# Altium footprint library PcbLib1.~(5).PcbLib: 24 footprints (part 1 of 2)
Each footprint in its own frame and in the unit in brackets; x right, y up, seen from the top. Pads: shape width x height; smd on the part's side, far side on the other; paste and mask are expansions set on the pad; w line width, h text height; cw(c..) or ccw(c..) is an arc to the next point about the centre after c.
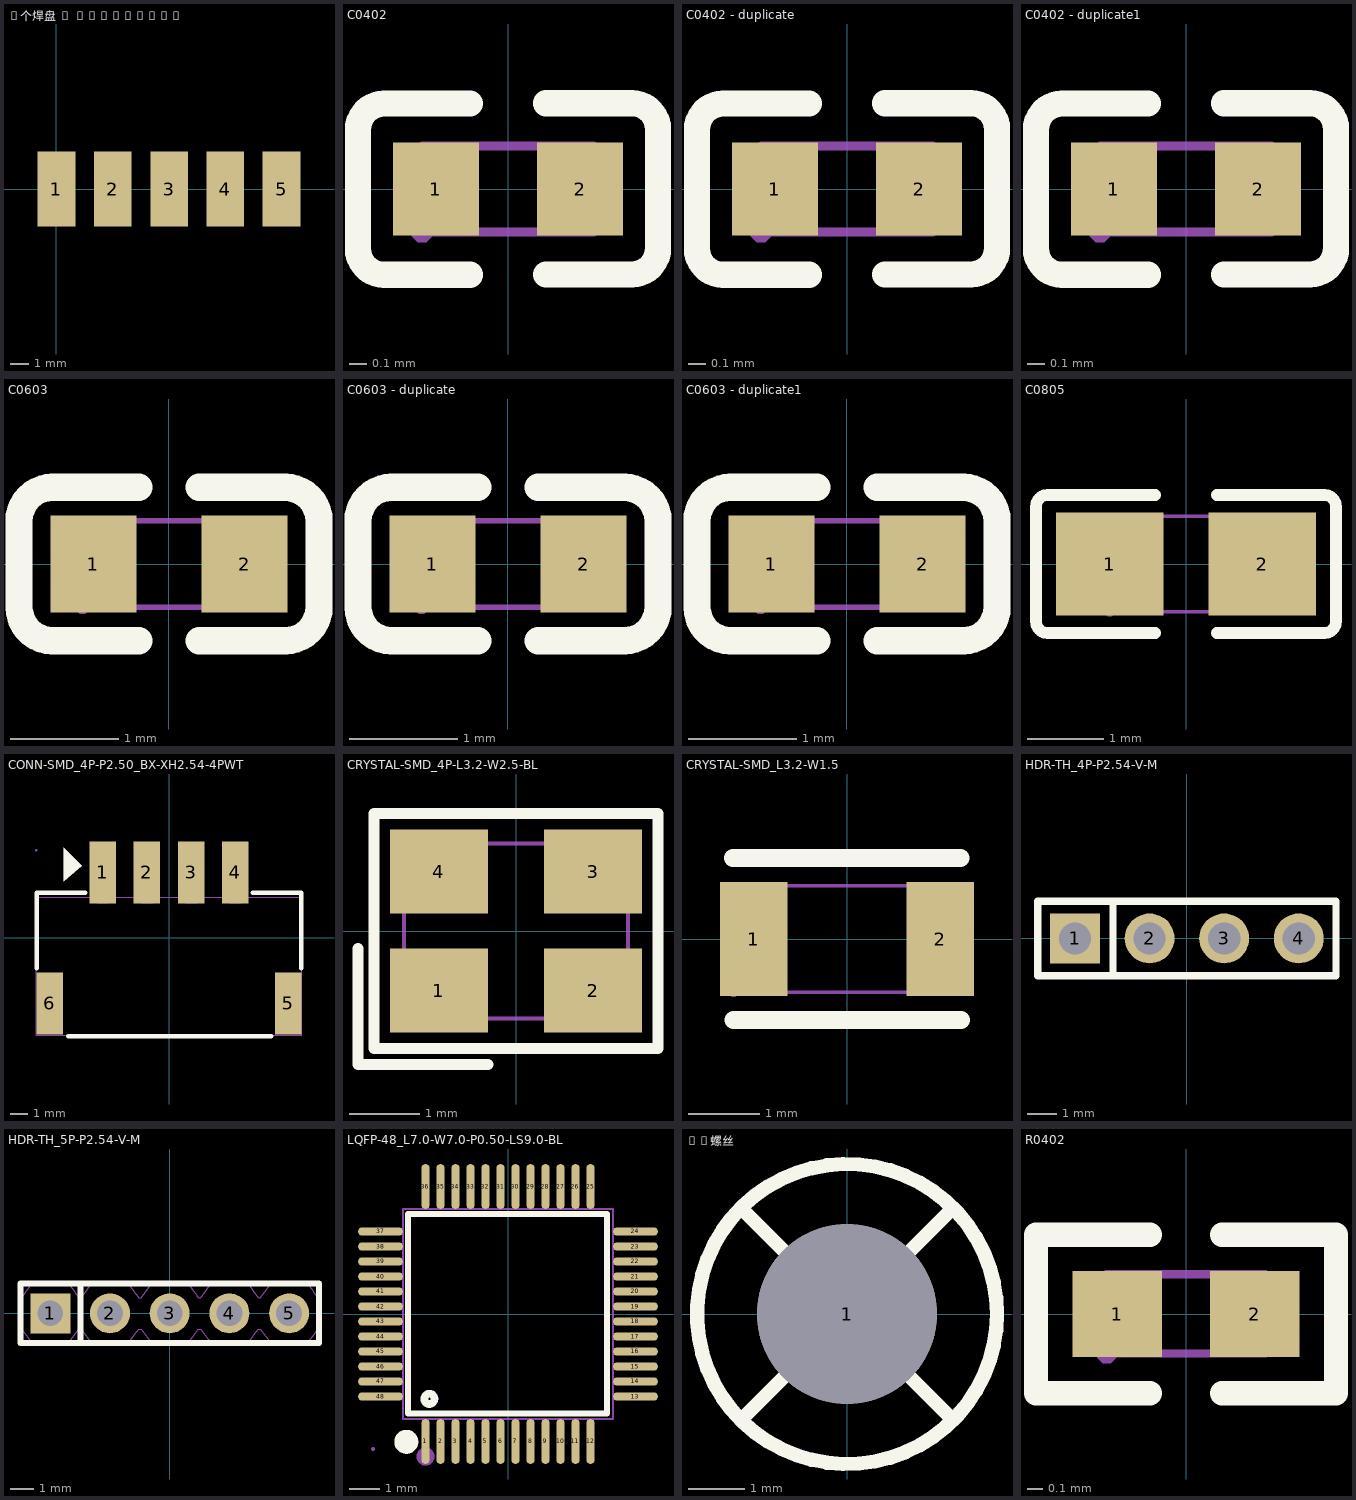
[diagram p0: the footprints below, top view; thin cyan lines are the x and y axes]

## 5个焊盘 - duplicate [mm]
pads (5):
  rect 2x4 smd: 1(0,0) 2(3,0) 3(6.001,0) 4(9,0) 5(12,0)

## C0402 [mm]
pads (2):
  rect 0.5x0.54 smd: 1(-0.42,0) 2(0.42,0)
Top Overlay:
  lines w0.152: -0.221,-0.5 -0.721,-0.5 cw(c-0.721,-0.347) -0.874,-0.347 -0.874,0.345 cw(c-0.721,0.345) -0.721,0.498 -0.221,0.498 ; 0.221,-0.498 0.721,-0.498 ccw(c0.721,-0.345) 0.874,-0.345 0.874,0.347 ccw(c0.721,0.347) 0.721,0.5 0.221,0.5
Mechanical 6:
  lines w0.051: -0.5,-0.25 0.5,-0.25 0.5,0.25 -0.5,0.25 -0.5,-0.25
Mechanical 8:
  region: -0.44,-0.25 -0.44,-0.275 -0.475,-0.31 -0.525,-0.31 -0.56,-0.275 -0.56,-0.25 -0.56,-0.225 -0.525,-0.19 -0.475,-0.19 -0.44,-0.225 -0.44,-0.25
Mechanical 9:
  region: 0.5,-0.25 0.5,0.25 0.25,0.25 0.25,-0.25
  region: -0.5,-0.25 -0.5,0.25 -0.25,0.25 -0.25,-0.25

## C0402 - duplicate [mm]
pads (2):
  rect 0.5x0.54 smd: 1(-0.42,0) 2(0.42,0)
Top Overlay:
  lines w0.152: -0.221,-0.5 -0.721,-0.5 cw(c-0.721,-0.347) -0.874,-0.347 -0.874,0.345 cw(c-0.721,0.345) -0.721,0.498 -0.221,0.498 ; 0.221,-0.498 0.721,-0.498 ccw(c0.721,-0.345) 0.874,-0.345 0.874,0.347 ccw(c0.721,0.347) 0.721,0.5 0.221,0.5
Mechanical 6:
  lines w0.051: -0.5,-0.25 -0.5,0.25 0.5,0.25 0.5,-0.25 -0.5,-0.25
Mechanical 8:
  region: -0.44,-0.25 -0.44,-0.275 -0.475,-0.31 -0.525,-0.31 -0.56,-0.275 -0.56,-0.25 -0.56,-0.225 -0.525,-0.19 -0.475,-0.19 -0.44,-0.225 -0.44,-0.25
Mechanical 9:
  region: -0.5,-0.25 -0.5,0.25 -0.25,0.25 -0.25,-0.25
  region: 0.5,-0.25 0.5,0.25 0.25,0.25 0.25,-0.25

## C0402 - duplicate1 [mm]
pads (2):
  rect 0.5x0.54 smd: 1(-0.42,0) 2(0.42,0)
Top Overlay:
  lines w0.152: -0.221,-0.5 -0.721,-0.5 cw(c-0.721,-0.347) -0.874,-0.347 -0.874,0.345 cw(c-0.721,0.345) -0.721,0.498 -0.221,0.498 ; 0.221,-0.498 0.721,-0.498 ccw(c0.721,-0.345) 0.874,-0.345 0.874,0.347 ccw(c0.721,0.347) 0.721,0.5 0.221,0.5
Mechanical 6:
  lines w0.051: -0.5,-0.25 -0.5,0.25 0.5,0.25 0.5,-0.25 -0.5,-0.25
Mechanical 8:
  region: -0.44,-0.25 -0.44,-0.275 -0.475,-0.31 -0.525,-0.31 -0.56,-0.275 -0.56,-0.25 -0.56,-0.225 -0.525,-0.19 -0.475,-0.19 -0.44,-0.225 -0.44,-0.25
Mechanical 9:
  region: -0.5,-0.25 -0.5,0.25 -0.25,0.25 -0.25,-0.25
  region: 0.5,-0.25 0.5,0.25 0.25,0.25 0.25,-0.25

## C0603 [mm]
pads (2):
  rect 0.8x0.9 smd: 1(-0.7,0) 2(0.7,0)
Top Overlay:
  lines w0.254: -1.08,-0.71 -0.28,-0.71 ; -1.08,0.71 -0.28,0.71 ; -1.08,-0.71 cw(c-1.08,-0.4) -1.39,-0.4 -1.39,0.4 cw(c-1.08,0.4) -1.08,0.71 ; 0.28,-0.71 1.08,-0.71 ccw(c1.08,-0.4) 1.39,-0.4 1.39,0.4 ccw(c1.08,0.4) 1.08,0.71 0.28,0.71
Mechanical 6:
  lines w0.051: -0.8,-0.4 0.8,-0.4 0.8,0.4 -0.8,0.4 -0.8,-0.4
Mechanical 8:
  region: -0.74,-0.4 -0.74,-0.425 -0.775,-0.46 -0.825,-0.46 -0.86,-0.425 -0.86,-0.4 -0.86,-0.375 -0.825,-0.34 -0.775,-0.34 -0.74,-0.375 -0.74,-0.4
Mechanical 9:
  region: 0.8,-0.4 0.8,0.4 0.5,0.4 0.5,-0.4
  region: -0.8,-0.4 -0.8,0.4 -0.5,0.4 -0.5,-0.4

## C0603 - duplicate [mm]
pads (2):
  rect 0.8x0.9 smd: 1(-0.7,0) 2(0.7,0)
Top Overlay:
  lines w0.254: -1.08,-0.71 -0.28,-0.71 ; -1.08,0.71 -0.28,0.71 ; -1.08,-0.71 cw(c-1.08,-0.4) -1.39,-0.4 -1.39,0.4 cw(c-1.08,0.4) -1.08,0.71 ; 0.28,-0.71 1.08,-0.71 ccw(c1.08,-0.4) 1.39,-0.4 1.39,0.4 ccw(c1.08,0.4) 1.08,0.71 0.28,0.71
Mechanical 6:
  lines w0.051: -0.8,-0.4 -0.8,0.4 0.8,0.4 0.8,-0.4 -0.8,-0.4
Mechanical 8:
  region: -0.74,-0.4 -0.74,-0.425 -0.775,-0.46 -0.825,-0.46 -0.86,-0.425 -0.86,-0.4 -0.86,-0.375 -0.825,-0.34 -0.775,-0.34 -0.74,-0.375 -0.74,-0.4
Mechanical 9:
  region: -0.8,-0.4 -0.8,0.4 -0.5,0.4 -0.5,-0.4
  region: 0.8,-0.4 0.8,0.4 0.5,0.4 0.5,-0.4

## C0603 - duplicate1 [mm]
pads (2):
  rect 0.8x0.9 smd: 1(-0.7,0) 2(0.7,0)
Top Overlay:
  lines w0.254: -1.08,-0.71 -0.28,-0.71 ; -1.08,0.71 -0.28,0.71 ; -1.08,-0.71 cw(c-1.08,-0.4) -1.39,-0.4 -1.39,0.4 cw(c-1.08,0.4) -1.08,0.71 ; 0.28,-0.71 1.08,-0.71 ccw(c1.08,-0.4) 1.39,-0.4 1.39,0.4 ccw(c1.08,0.4) 1.08,0.71 0.28,0.71
Mechanical 6:
  lines w0.051: -0.8,-0.4 -0.8,0.4 0.8,0.4 0.8,-0.4 -0.8,-0.4
Mechanical 8:
  region: -0.74,-0.4 -0.74,-0.425 -0.775,-0.46 -0.825,-0.46 -0.86,-0.425 -0.86,-0.4 -0.86,-0.375 -0.825,-0.34 -0.775,-0.34 -0.74,-0.375 -0.74,-0.4
Mechanical 9:
  region: -0.8,-0.4 -0.8,0.4 -0.5,0.4 -0.5,-0.4
  region: 0.8,-0.4 0.8,0.4 0.5,0.4 0.5,-0.4

## C0805 [mm]
pads (2):
  rect 1.41x1.35 smd paste-100 mask+0.051: 1(-1,0) 2(1,0)
Top Overlay:
  lines w0.152: -0.401,-0.904 -1.811,-0.904 cw(c-1.811,-0.751) -1.964,-0.751 -1.964,0.751 cw(c-1.811,0.751) -1.811,0.904 -0.401,0.904 ; 0.401,-0.904 1.811,-0.904 ccw(c1.811,-0.751) 1.964,-0.751 1.964,0.751 ccw(c1.811,0.751) 1.811,0.904 0.401,0.904
Top Paste:
  region: -1.705,-0.64 -1.705,0.64 -1.655,0.69 -0.505,0.69 -0.455,0.64 -0.45,0.23 -0.9,0.23 -0.9,-0.22 -0.46,-0.22 -0.455,-0.64 -0.505,-0.69 -1.655,-0.69
  region: 1.705,0.64 1.705,-0.64 1.655,-0.69 0.505,-0.69 0.455,-0.64 0.45,-0.23 0.9,-0.23 0.9,0.22 0.46,0.22 0.455,0.64 0.505,0.69 1.655,0.69
Mechanical 6:
  lines w0.051: -1,-0.625 -1,0.625 1,0.625 1,-0.625 -1,-0.625
Mechanical 8:
  region: -0.94,-0.625 -0.94,-0.65 -0.975,-0.685 -1.025,-0.685 -1.06,-0.65 -1.06,-0.625 -1.06,-0.6 -1.025,-0.565 -0.975,-0.565 -0.94,-0.6 -0.94,-0.625
Mechanical 9:
  region: -1,-0.625 -1,0.625 -0.5,0.625 -0.5,-0.625
  region: 1,0.625 1,-0.625 0.5,-0.625 0.5,0.625

## CONN-SMD_4P-P2.50_BX-XH2.54-4PWT [mm]
pads (6):
  rect 1.5x3.5 smd paste+0 mask+0.05: 1(-3.75,3.7) 2(-1.25,3.7) 3(1.25,3.7) 4(3.75,3.7) 5(6.73,-3.7) 6(-6.73,-3.7)
Top Overlay:
  region: -4.946,4.081 -5.962,5.097 -5.962,3.192
  lines w0.254: -7.486,-1.719 -7.486,2.557 -4.731,2.557 ; -5.708,-5.571 5.783,-5.571 ; 4.73,2.558 6.389,2.558 7.486,2.558 7.486,-1.719
Mechanical 2:
  region: -4.946,4.081 -5.962,5.097 -5.962,3.192
Mechanical 6:
  lines w0.051: -7.5,-5.502 7.5,-5.502 7.5,2.298 -7.5,2.298 -7.5,-5.502
Mechanical 8:
  region: -7.44,4.95 -7.44,4.925 -7.475,4.89 -7.525,4.89 -7.56,4.925 -7.56,4.95 -7.56,4.975 -7.525,5.01 -7.475,5.01 -7.44,4.975 -7.44,4.95
Mechanical 9:
  region: 6.53,-2.45 6.93,-2.45 6.93,-4.95 6.53,-4.95
  region: -6.93,-2.45 -6.53,-2.45 -6.53,-4.95 -6.93,-4.95
  region: 3.43,4.95 4.07,4.95 4.07,1.95 3.43,1.95
  region: 0.93,4.95 1.57,4.95 1.57,1.95 0.93,1.95
  region: -1.57,4.95 -0.93,4.95 -0.93,1.95 -1.57,1.95
  region: -4.07,4.95 -3.43,4.95 -3.43,1.95 -4.07,1.95

## CRYSTAL-SMD_4P-L3.2-W2.5-BL [mm]
pads (4):
  rect 1.4x1.2 smd: 1(-1.1,-0.85) 2(1.1,-0.85) 3(1.1,0.85) 4(-1.1,0.85)
Top Overlay:
  lines w0.152: -2.257,-0.25 -2.257,-1.907 -0.4,-1.907 ; -2.029,-1.678 -2.029,1.679 2.029,1.679 2.029,-1.678 -2.029,-1.678
Mechanical 2:
  circle w0.254: c-1.27,-0.889 r0.127
Mechanical 6:
  lines w0.051: -1.6,-1.25 -1.6,1.25 1.6,1.25 1.6,-1.25 -1.6,-1.25
Mechanical 8:
  region: -1.54,-1.25 -1.54,-1.275 -1.575,-1.31 -1.625,-1.31 -1.66,-1.275 -1.66,-1.25 -1.66,-1.225 -1.625,-1.19 -1.575,-1.19 -1.54,-1.225 -1.54,-1.25
Mechanical 9:
  region: -1.5,1.15 -0.6,1.15 -0.6,0.35 -1.5,0.35
  region: 0.6,1.15 1.5,1.15 1.5,0.35 0.6,0.35
  region: 0.6,-0.35 1.5,-0.35 1.5,-1.15 0.6,-1.15
  region: -1.5,-0.35 -0.6,-0.35 -0.6,-1.15 -1.5,-1.15

## CRYSTAL-SMD_L3.2-W1.5 [mm]
pads (2):
  rect 0.95x1.6 smd: 1(-1.308,0) 2(1.308,0)
Top Overlay:
  lines w0.254: -1.603,1.14 1.597,1.14 ; -1.597,-1.14 1.603,-1.14
Mechanical 6:
  lines w0.051: -1.597,-0.75 1.603,-0.75 1.603,0.75 -1.597,0.75 -1.597,-0.75
Mechanical 8:
  region: -1.537,-0.75 -1.537,-0.775 -1.573,-0.81 -1.622,-0.81 -1.657,-0.775 -1.657,-0.75 -1.657,-0.725 -1.622,-0.69 -1.573,-0.69 -1.537,-0.725 -1.537,-0.75
Mechanical 9:
  region: -1.598,-0.65 -1.598,0.65 -0.847,0.65 -0.847,-0.65
  region: 0.853,-0.65 0.853,0.65 1.603,0.65 1.603,-0.65

## HDR-TH_4P-P2.54-V-M [mm]
pads (4):
  rect 1.7x1.7 hole 1.1: 1(-3.81,0)
  round 1.7 hole 1.1: 2(-1.27,0) 3(1.27,0) 4(3.81,0)
Top Overlay:
  lines w0.254: -2.516,-1.27 -2.516,1.27 ; -2.516,1.27 -5.08,1.27 -5.08,-1.27 5.08,-1.27 5.08,1.27 -2.516,1.27
Mechanical 6:
  lines w0.051: -5.08,-1.25 5.08,-1.25 5.08,1.25 -5.08,1.25 -5.08,-1.25
Mechanical 8:
  region: -5.02,-1.25 -5.02,-1.275 -5.055,-1.31 -5.105,-1.31 -5.14,-1.275 -5.14,-1.25 -5.14,-1.225 -5.105,-1.19 -5.055,-1.19 -5.02,-1.225 -5.02,-1.25
Mechanical 9:
  region: 3.49,0.32 4.13,0.32 4.13,-0.32 3.49,-0.32
  region: 0.95,0.32 1.59,0.32 1.59,-0.32 0.95,-0.32
  region: -1.59,0.32 -0.95,0.32 -0.95,-0.32 -1.59,-0.32
  region: -4.13,0.32 -3.49,0.32 -3.49,-0.32 -4.13,-0.32

## HDR-TH_5P-P2.54-V-M [mm]
pads (5):
  rect 1.7x1.7 hole 1.1: 1(-5.08,0)
  round 1.7 hole 1.1: 2(-2.54,0) 3(0,0) 4(2.54,0) 5(5.08,0)
Top Overlay:
  lines w0.254: -3.786,-1.27 -3.786,1.27 ; -6.35,-1.27 -6.35,1.27 6.35,1.27 6.35,-1.27 -6.35,-1.27
Mechanical 6:
  lines w0.051: -6.35,-0.67 -6.35,-0.67 -6.3,-0.67 -5.85,-1.27 -4.31,-1.27 -4.077,-0.965 -3.86,-0.67 -3.76,-0.67 -3.31,-1.27 -1.77,-1.27 -1.542,-0.972 -1.503,-0.919 -1.32,-0.67 -1.22,-0.67 -0.77,-1.27 0.77,-1.27 0.992,-0.98 1.02,-0.942 1.22,-0.67 1.32,-0.67 1.77,-1.27 3.31,-1.271 3.51,-1.009 3.545,-0.963 3.581,-0.913 3.759,-0.67 3.86,-0.67 4.31,-1.27 5.85,-1.27 6.075,-0.976 6.3,-0.67 6.35,-0.67 6.35,0.67 6.3,0.67 6.112,0.925 6.079,0.97 5.85,1.27 4.311,1.27 3.86,0.67 3.76,0.67 3.533,0.979 3.458,1.076 3.31,1.27 1.77,1.27 1.32,0.67 1.22,0.67 1.136,0.783 1.108,0.822 1.01,0.955 0.867,1.143 0.77,1.27 -0.77,1.27 -1.22,0.67 -1.32,0.67 -1.417,0.801 -1.436,0.827 -1.459,0.859 -1.546,0.976 -1.631,1.088 -1.77,1.27 -3.31,1.27 -3.76,0.67 -3.86,0.67 -4.017,0.884 -4.048,0.925 -4.149,1.059 -4.31,1.27 -5.85,1.27 -6.028,1.032 -6.299,0.67 -6.35,0.67 -6.35,-0.67 ; -6.35,-0.67 -6.35,-0.67
Mechanical 8:
  region: -6.29,-1.271 -6.29,-1.296 -6.325,-1.331 -6.375,-1.331 -6.41,-1.296 -6.41,-1.271 -6.41,-1.246 -6.375,-1.211 -6.325,-1.211 -6.29,-1.246 -6.29,-1.271
Mechanical 9:
  region: -5.4,0.32 -4.76,0.32 -4.76,-0.32 -5.4,-0.32
  region: -2.86,0.32 -2.22,0.32 -2.22,-0.32 -2.86,-0.32
  region: -0.32,0.32 0.32,0.32 0.32,-0.32 -0.32,-0.32
  region: 2.22,0.32 2.86,0.32 2.86,-0.32 2.22,-0.32
  region: 4.76,0.32 5.4,0.32 5.4,-0.32 4.76,-0.32

## LQFP-48_L7.0-W7.0-P0.50-LS9.0-BL [mm]
pads (48):
  oval 0.27x1.5 smd paste+0 mask+0.05: 1(-2.75,-4.25) 2(-2.25,-4.25) 3(-1.75,-4.25) 4(-1.25,-4.25) 5(-0.75,-4.25) 6(-0.25,-4.25) 7(0.25,-4.25) 8(0.75,-4.25) 9(1.25,-4.25) 10(1.75,-4.25) 11(2.25,-4.25) 12(2.75,-4.25) 25(2.75,4.25) 26(2.25,4.25) 27(1.75,4.25) 28(1.25,4.25) 29(0.75,4.25) 30(0.25,4.25) 31(-0.25,4.25) 32(-0.75,4.25) 33(-1.25,4.25) 34(-1.75,4.25) 35(-2.25,4.25) 36(-2.75,4.25)
  oval 1.5x0.27 smd paste+0 mask+0.05: 13(4.25,-2.75) 14(4.25,-2.25) 15(4.25,-1.75) 16(4.25,-1.25) 17(4.25,-0.75) 18(4.25,-0.25) 19(4.25,0.25) 20(4.25,0.75) 21(4.25,1.25) 22(4.25,1.75) 23(4.25,2.25) 24(4.25,2.75) 37(-4.25,2.75) 38(-4.25,2.25) 39(-4.25,1.75) 40(-4.25,1.25) 41(-4.25,0.75) 42(-4.25,0.25) 43(-4.25,-0.25) 44(-4.25,-0.75) 45(-4.25,-1.25) 46(-4.25,-1.75) 47(-4.25,-2.25) 48(-4.25,-2.75)
Top Overlay:
  circle w0.254: c-2.62,-2.83 r0.17
  lines w0.2: -2.896,3.34 3.302,3.34 3.302,-3.315 -3.327,-3.315 -3.327,3.34 -2.565,3.34
  lines w0.4: -3.39,-4.06 ccw(c-3.389,-4.26) -3.387,-4.06
Mechanical 2:
  circle w0.3: c-2.75,-4.75 r0.15
Mechanical 6:
  lines w0.051: -3.5,-3.5 -3.5,3.5 3.5,3.5 3.5,-3.5 -3.5,-3.5
Mechanical 7:
  drawing of 48 lines, arcs and shapes, not listed
Mechanical 8:
  region: -4.44,-4.5 -4.44,-4.525 -4.475,-4.56 -4.525,-4.56 -4.56,-4.525 -4.56,-4.5 -4.56,-4.475 -4.525,-4.44 -4.475,-4.44 -4.44,-4.475 -4.44,-4.5
Mechanical 9:
  drawing of 48 lines, arcs and shapes, not listed

## M3螺丝 [mil]
pads (1):
  round 126 hole 126 paste-99999 mask+4: 1(0,0)
Top Overlay:
  circle w10: c0,0 r105
  lines w10: -72.5,-72.5 72.5,72.5 ; -72.5,72.5 72.5,-72.5

## R0402 [mm]
pads (2):
  rect 0.566x0.54 smd paste-100 mask+0.051: 1(-0.433,0) 2(0.433,0)
Top Overlay:
  lines w0.152: -0.226,-0.499 -0.944,-0.499 -0.944,0.499 -0.226,0.499 ; 0.226,-0.499 0.944,-0.499 0.944,0.499 0.226,0.499
Top Paste:
  region: -0.135,-0.23 -0.135,0.23 -0.175,0.27 -0.676,0.27 -0.716,0.23 -0.716,-0.23 -0.676,-0.27 -0.175,-0.27
  region: 0.135,-0.23 0.135,0.23 0.175,0.27 0.676,0.27 0.716,0.23 0.716,-0.23 0.676,-0.27 0.175,-0.27
Mechanical 6:
  lines w0.051: -0.5,-0.25 0.5,-0.25 0.5,0.25 -0.5,0.25 -0.5,-0.25
Mechanical 8:
  region: -0.44,-0.25 -0.44,-0.275 -0.475,-0.31 -0.525,-0.31 -0.56,-0.275 -0.56,-0.25 -0.56,-0.225 -0.525,-0.19 -0.475,-0.19 -0.44,-0.225 -0.44,-0.25
Mechanical 9:
  region: -0.249,0.25 -0.249,-0.25 -0.499,-0.25 -0.499,0.25
  region: 0.251,-0.25 0.251,0.25 0.501,0.25 0.501,-0.25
